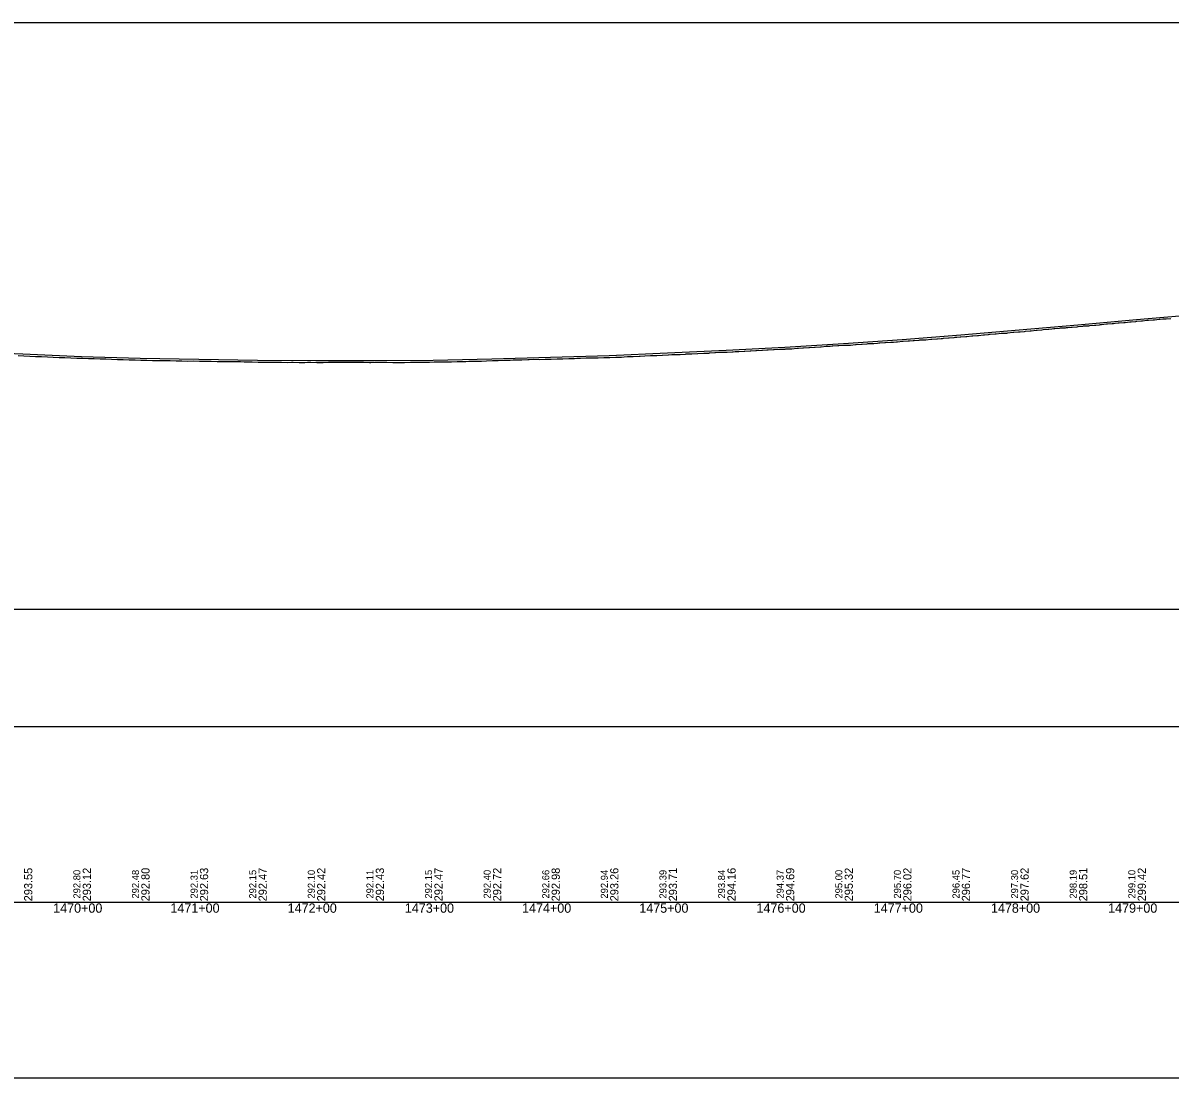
# Model space of a CAD drawing. Extents: x -3627 to 47473, y 2850 to 4350.
# Drawn here: x 34427 to 35406, y 2850 to 3750 of the extents above; entities that cross this region are included whole.
import ezdxf

# ---------------------------------------------------------------- set-up
doc = ezdxf.new("R2010")
doc.units = 0
for name, color, linetype in [('RD_DDB_Profile_EX', 7, 'Continuous'), ('RD_DDB_Profile_PR', 7, 'Continuous'), ('RD_DDB_StaTX', 7, 'Continuous'), ('RD_DDB_StripGrade', 7, 'Continuous'), ('RD_GPK_Profile_Cell', 7, 'Continuous'), ('RD_SHT_ShtClip', 7, 'Continuous')]:
    doc.layers.add(name, color=color, linetype=linetype)

msp = doc.modelspace()

# ---------------------------------------------------------------- linework, layer by layer
at = {"layer": 'RD_DDB_Profile_EX'}
for points in [[(35148.266577, 3476.452355), (35152.630962, 3476.49859), (35153.277738, 3476.550435), (35156.502076, 3476.939115), (35157.622784, 3477.07427), (35158.277729, 3477.10714), (35162.623068, 3477.49948), (35163.287176, 3477.539425), (35167.622241, 3477.67171), (35168.298374, 3477.719365), (35170.016711, 3477.84025), (35172.620849, 3478.023575), (35173.308452, 3478.07186), (35177.619734, 3478.5481), (35178.321548, 3478.59033), (35182.568921, 3478.898565), (35183.531347, 3478.96607), (35186.860973, 3479.19974), (35187.571958, 3479.26387), (35191.859965, 3479.521465), (35192.575073, 3479.557275), (35197.045982, 3479.79014), (35197.568132, 3479.837375), (35201.843739, 3480.179985), (35202.571326, 3480.245695), (35206.837685, 3480.58836), (35207.574477, 3480.632665), (35210.560617, 3480.872855), (35211.823613, 3480.974505), (35212.569144, 3481.026925), (35216.820165, 3481.410145), (35217.570933, 3481.470535), (35221.811422, 3481.81098), (35222.574173, 3481.849215), (35224.075253, 3481.969695), (35226.799639, 3482.188445), (35227.569057, 3482.28102), (35231.794958, 3482.577695), (35232.570889, 3482.64018), (35236.780421, 3483.02064), (35237.589888, 3483.093175), (35241.779169, 3483.38686), (35242.56937, 3483.44251), (35246.777001, 3483.82158), (35247.571324, 3483.9092), (35251.104523, 3484.3697), (35251.766249, 3484.455975), (35252.566478, 3484.5282), (35256.759812, 3484.864775), (35257.570068, 3484.93792), (35261.757119, 3485.27344), (35262.572067, 3485.355345), (35264.619159, 3485.43776), (35266.744068, 3485.523405), (35267.5674, 3485.58125), (35271.740888, 3486.124665), (35272.56947, 3486.207985), (35276.723394, 3486.459305), (35277.564817, 3486.535395), (35278.133794, 3486.58674), (35281.718588, 3486.910425), (35282.56864, 3486.95328), (35286.713426, 3487.36867), (35287.570751, 3487.446295), (35291.698406, 3487.81938), (35292.566329, 3487.94116), (35296.696501, 3488.354775), (35297.568557, 3488.42511), (35301.687681, 3488.837595), (35302.564327, 3488.89055), (35305.163065, 3489.124675), (35306.68458, 3489.261815), (35307.568356, 3489.359445), (35311.672536, 3489.730185), (35312.562443, 3489.81965), (35316.6676, 3490.066765), (35317.566525, 3490.121185), (35318.6777, 3490.19933), (35321.654814, 3490.408835), (35322.560693, 3490.49092), (35326.648596, 3490.90071), (35327.56491, 3490.99239), (35331.637811, 3491.483015), (35332.192335, 3491.532945), (35332.560977, 3491.566155), (35336.633985, 3491.730275), (35337.563454, 3491.804895), (35341.623892, 3492.130895), (35342.55969, 3492.19653), (35345.706971, 3492.57508), (35346.61973, 3492.684915), (35347.562182, 3492.77947), (35351.615765, 3493.22536), (35352.558628, 3493.366925), (35356.62162, 3493.69111), (35357.561306, 3493.7572), (35359.221606, 3493.9398), (35361.617085, 3494.203385), (35362.557831, 3494.28808), (35366.622586, 3494.53147), (35367.560625, 3494.61629)], [(35367.560625, 3494.61629), (35371.617423, 3495.10328), (35372.736241, 3495.189405), (35376.61743, 3495.42267), (35377.560035, 3495.5174), (35381.611043, 3495.963375), (35382.556711, 3496.039285), (35386.250877, 3496.334485), (35386.614372, 3496.36355), (35387.559635, 3496.43962), (35391.606756, 3496.76385), (35392.556433, 3496.84964), (35396.608937, 3497.254665), (35397.559433, 3497.340675), (35399.765512, 3497.495325), (35401.600854, 3497.624085), (35402.556325, 3497.70054), (35406.596135, 3498.025345)], [(34899.724005, 3463.92016), (34902.960706, 3464.138825), (34907.957486, 3464.235645), (34913.23864, 3464.34846), (34917.968098, 3464.444435), (34922.972345, 3464.497575), (34926.753275, 3464.687625), (34927.980024, 3464.74687), (34932.988305, 3464.99613), (34937.993726, 3465.010225), (34940.267911, 3465.192525), (34942.998997, 3465.39554), (34947.995901, 3465.557685), (34953.002176, 3465.85627), (34953.782546, 3465.887655), (34958.009495, 3466.05788), (34962.718199, 3466.201195), (34963.019793, 3466.20731), (34967.297181, 3466.422165), (34967.717473, 3466.443295), (34968.026839, 3466.45567), (34972.71663, 3466.69134), (34973.034936, 3466.710475), (34977.71571, 3466.992505), (34978.042153, 3467.01213), (34980.811817, 3467.068505), (34982.704797, 3467.107125), (34983.041034, 3467.123955), (34987.703672, 3467.2192), (34988.049879, 3467.21576), (34992.702557, 3467.589155), (34993.0587, 3467.61765), (34994.326452, 3467.65612), (34997.701248, 3467.758675), (34998.068252, 3467.773385), (35002.699851, 3467.91424), (35003.077506, 3467.92947), (35008.087292, 3468.31624), (35012.695896, 3468.45624), (35013.098007, 3468.48443), (35017.685065, 3468.807955), (35018.099436, 3468.83286), (35021.355723, 3469.061995), (35022.683335, 3469.15546), (35023.110468, 3469.18115), (35027.6814, 3469.18364), (35028.121233, 3469.19695), (35032.679752, 3469.517455), (35033.130275, 3469.549135), (35034.870358, 3469.61966), (35037.677526, 3469.73358), (35038.142512, 3469.756945), (35042.675301, 3470.076655), (35043.155062, 3470.09115), (35047.673092, 3470.27407), (35048.384993, 3470.31492), (35052.661565, 3470.53158), (35053.17123, 3470.56746), (35057.658074, 3470.884125), (35058.18468, 3470.91059), (35061.899629, 3471.097865), (35062.656718, 3471.136065), (35063.195926, 3471.179455), (35067.654979, 3471.44929), (35068.207575, 3471.47711), (35072.656812, 3471.655105), (35073.211311, 3471.688675), (35075.414264, 3471.776975), (35077.649512, 3471.866695), (35078.206298, 3471.88365), (35082.651054, 3472.106125), (35083.209584, 3472.134335), (35087.651475, 3472.489825), (35088.214354, 3472.523885), (35088.928899, 3472.559645), (35092.652643, 3472.74618), (35093.219652, 3472.78611), (35097.645049, 3473.052575), (35098.216515, 3473.09865), (35102.646127, 3473.40918), (35103.22215, 3473.45557), (35107.647071, 3473.810235), (35108.227486, 3473.839615), (35112.646842, 3474.19372), (35113.234371, 3474.229325), (35115.95817, 3474.420685), (35117.638726, 3474.538825), (35118.231339, 3474.56847), (35122.639829, 3474.83365), (35123.237781, 3474.875515), (35127.640934, 3475.00851), (35128.242997, 3475.04472), (35129.472805, 3475.09419), (35132.640647, 3475.221795), (35133.250572, 3475.25856), (35137.631424, 3475.611585), (35138.25191, 3475.64886), (35142.632254, 3475.91277), (35143.259403, 3475.963), (35147.632823, 3476.40149), (35148.266577, 3476.452355)], [(34423.172913, 3466.34095), (34428.172413, 3466.093615), (34433.168372, 3465.846545), (34438.167864, 3465.501195), (34443.167098, 3465.39751), (34448.166589, 3465.198045), (34453.166078, 3464.942495), (34458.165565, 3464.75315), (34463.165051, 3464.60166), (34468.164535, 3464.45219), (34473.164018, 3464.154705), (34478.163646, 3463.951175), (34483.163125, 3463.757615), (34488.15303, 3463.652235), (34493.178653, 3463.506835)], [(34493.178653, 3463.506835), (34497.976879, 3463.354995), (34502.961929, 3463.16175), (34507.960851, 3463.060585), (34512.959948, 3462.9149), (34517.959045, 3462.76182), (34522.953487, 3462.520195), (34527.952584, 3462.369015), (34532.951681, 3462.26961), (34537.950778, 3462.17714), (34542.949875, 3462.025955), (34547.94447, 3461.980285), (34552.943238, 3461.974235), (34557.942489, 3461.831295), (34562.941586, 3461.73346), (34567.936174, 3461.63445), (34572.93527, 3461.681895), (34577.929844, 3461.5287), (34582.924407, 3461.434545), (34587.923501, 3461.38796), (34592.918177, 3461.292005), (34597.917268, 3461.145235), (34602.9118, 3461.14654), (34607.911008, 3461.19072), (34612.905746, 3461.09597), (34615.916663, 3460.975865), (34617.904673, 3460.90138), (34622.903188, 3460.90218), (34627.906417, 3460.754455), (34629.431298, 3460.72362), (34632.908591, 3460.652465), (34637.910351, 3460.55432), (34642.945933, 3460.547765), (34647.912642, 3460.59741), (34652.913047, 3460.499895), (34656.460569, 3460.53535), (34657.913175, 3460.5475), (34662.912222, 3460.50059), (34667.91127, 3460.49874), (34669.975204, 3460.519635), (34672.909523, 3460.55093), (34677.907106, 3460.50104), (34682.894982, 3460.45005), (34683.489839, 3460.46211), (34687.891382, 3460.554185), (34692.887629, 3460.554035), (34697.004475, 3460.555665), (34697.883648, 3460.559165), (34702.878384, 3460.70886), (34707.873329, 3460.514165), (34710.51911, 3460.56727), (34712.872256, 3460.612315), (34717.865893, 3460.61721), (34722.859545, 3460.47179), (34724.033745, 3460.49601), (34727.852195, 3460.57465), (34732.844549, 3460.57782), (34737.836885, 3460.58118), (34742.828036, 3460.386985), (34747.823793, 3460.48767), (34751.063016, 3460.48775), (34752.823694, 3460.488585), (34757.818119, 3460.64106), (34762.812519, 3460.594355), (34764.577651, 3460.612275), (34767.810727, 3460.645625), (34772.803806, 3460.599085), (34774.163434, 3460.65446), (34778.092287, 3460.80111), (34782.799955, 3460.802175), (34787.806937, 3460.904), (34791.606922, 3461.0193), (34792.814159, 3461.05572), (34797.81899, 3461.1069), (34802.826952, 3461.30815), (34805.121557, 3461.354485), (34807.832254, 3461.40983), (34812.84119, 3461.513305), (34817.846971, 3461.614145), (34818.636193, 3461.638155), (34822.856728, 3461.76835), (34827.863502, 3462.01672), (34832.150828, 3462.018785), (34832.87354, 3462.02419), (34837.881237, 3462.224245), (34842.888998, 3462.37634), (34845.665463, 3462.54427), (34847.900299, 3462.672815), (34852.908761, 3462.681905), (34857.920559, 3462.88364), (34859.180099, 3462.934605), (34862.920307, 3463.084385), (34867.933109, 3463.03956), (34872.936676, 3463.23452), (34877.941325, 3463.28933), (34882.9428, 3463.435465), (34886.209369, 3463.533905), (34887.94756, 3463.58636), (34892.952846, 3463.695685), (34897.955208, 3463.796025), (34899.724005, 3463.92016)]]:
    msp.add_lwpolyline(points, dxfattribs=at)
at = {"layer": 'RD_DDB_Profile_PR'}
msp.add_lwpolyline([(34377.33, 3469.7025), (34427.33, 3467.7355), (34477.33, 3465.585), (34527.33, 3463.988), (34577.33, 3463.147), (34627.33, 3462.3715), (34677.33, 3462.107), (34727.33, 3462.164), (34777.33, 3462.3725), (34827.33, 3463.5905), (34877.33, 3464.8825), (34927.33, 3466.3155), (34977.33, 3468.5695), (35027.33, 3470.7835), (35077.33, 3473.454), (35127.33, 3476.599), (35177.33, 3480.116), (35227.33, 3483.8525), (35277.33, 3488.114), (35327.33, 3492.569), (35377.33, 3497.0945), (35427.33, 3501.3395)], dxfattribs=at)
at = {"layer": 'RD_GPK_Profile_Cell'}
msp.add_line((1000, 3000), (46705.077602, 3000), dxfattribs=at)
at = {"layer": 'RD_SHT_ShtClip'}
for points in [[(33953.33, 3750), (33953.33, 3250), (35453.33, 3250), (35453.33, 3250), (35453.33, 3750), (35453.33, 3750)], [(33933.33, 3150), (35473.33, 3150), (35473.33, 2850), (33933.33, 2850)]]:
    msp.add_lwpolyline(points, close=True, dxfattribs=at)

# ---------------------------------------------------------------- texts
at = {"layer": 'RD_DDB_StaTX'}
for s, p in [('1470+00', (34453.125471, 2991)), ('1471+00', (34553.125471, 2991)), ('1472+00', (34653.125471, 2991)), ('1473+00', (34753.125471, 2991)), ('1474+00', (34853.125471, 2991)), ('1475+00', (34953.125471, 2991)), ('1476+00', (35053.125471, 2991)), ('1477+00', (35153.125471, 2991)), ('1478+00', (35253.125471, 2991)), ('1479+00', (35353.125471, 2991))]:
    msp.add_text(s, height=8, dxfattribs=at).set_placement(p)
at = {"layer": 'RD_DDB_StripGrade'}
for s, height, p in [('293.55', 7, (34435.33, 3000.75)), ('292.80', 6, (34476.33, 3003.073688)), ('293.12', 7, (34485.33, 3000.75)), ('292.48', 6, (34526.33, 3003.073688)), ('292.80', 7, (34535.33, 3000.75)), ('292.31', 6, (34576.33, 3003.073688)), ('292.63', 7, (34585.33, 3000.75)), ('292.15', 6, (34626.33, 3003.073688)), ('292.47', 7, (34635.33, 3000.75)), ('292.10', 6, (34676.33, 3003.073688)), ('292.42', 7, (34685.33, 3000.75)), ('292.11', 6, (34726.33, 3003.073688)), ('292.43', 7, (34735.33, 3000.75)), ('292.15', 6, (34776.33, 3003.073688)), ('292.47', 7, (34785.33, 3000.75)), ('292.40', 6, (34826.33, 3003.073688)), ('292.72', 7, (34835.33, 3000.75)), ('292.66', 6, (34876.33, 3003.073688)), ('292.98', 7, (34885.33, 3000.75)), ('292.94', 6, (34926.33, 3003.073688)), ('293.26', 7, (34935.33, 3000.75)), ('293.39', 6, (34976.33, 3003.073688)), ('293.71', 7, (34985.33, 3000.75)), ('293.84', 6, (35026.33, 3003.073688)), ('294.16', 7, (35035.33, 3000.75)), ('294.37', 6, (35076.33, 3003.073688)), ('294.69', 7, (35085.33, 3000.75)), ('295.00', 6, (35126.33, 3003.073688)), ('295.32', 7, (35135.33, 3000.75)), ('295.70', 6, (35176.33, 3003.073688)), ('296.02', 7, (35185.33, 3000.75)), ('296.45', 6, (35226.33, 3003.073688)), ('296.77', 7, (35235.33, 3000.75)), ('297.30', 6, (35276.33, 3003.073688)), ('297.62', 7, (35285.33, 3000.75)), ('298.19', 6, (35326.33, 3003.073688)), ('298.51', 7, (35335.33, 3000.75)), ('299.10', 6, (35376.33, 3003.073688)), ('299.42', 7, (35385.33, 3000.75))]:
    msp.add_text(s, height=height, rotation=90, dxfattribs=at).set_placement(p)

doc.saveas('drawing.dxf')
